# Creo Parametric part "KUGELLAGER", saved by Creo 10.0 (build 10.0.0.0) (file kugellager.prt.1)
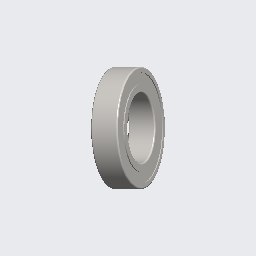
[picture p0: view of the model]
Units: millimeter Newton Second (mmNs); MM, TONNE, SECS

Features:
  1. coordinate system "KUGELLAGER"
  2. imported feature "Import-ke ID 4"

Other named items: NOTE_0

Notes: SS-61801-ZZ-MAE

Surfaces: 16 torus, 12 cylinder, 6 plane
